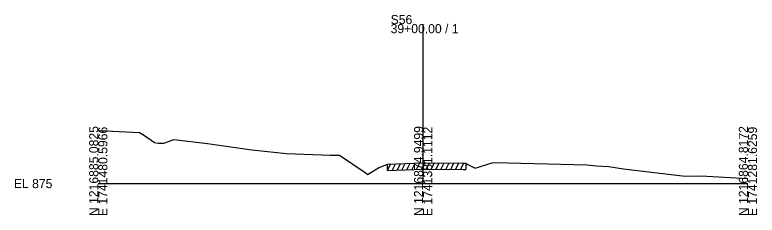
# Model space of a CAD drawing. Extents: x -26 to 1203, y -10 to 19541.
# Drawn here: x -25.7 to 202.8, y 13990.3 to 14051.9 of the extents above; entities that cross this region are included whole.
import ezdxf

# ---------------------------------------------------------------- set-up
doc = ezdxf.new("R2010")
doc.units = 0
for name, color, linetype in [('RD_GPK_XS_Cell', 7, 'Continuous'), ('RD_XS_ExGround', 7, 'Continuous'), ('RD_XS_ExPaveRet', 7, 'Continuous'), ('RD_XS_TX_Elev_EX', 7, 'Continuous')]:
    doc.layers.add(name, color=color, linetype=linetype)

msp = doc.modelspace()

# ---------------------------------------------------------------- linework, layer by layer
at = {"layer": 'RD_GPK_XS_Cell'}
for p, q in [((100, 14000), (100, 14049.04)), ((0, 14000), (100, 14000)), ((100, 14000), (200, 14000))]:
    msp.add_line(p, q, dxfattribs=at)
at = {"layer": 'RD_XS_ExGround'}
msp.add_lwpolyline([(0, 14016.35), (2.37, 14016.18), (12.64, 14015.72), (13.87, 14014.98), (17.32, 14012.67), (18.41, 14012.42), (20.14, 14012.39), (21.58, 14012.99), (23.3, 14013.59), (33.58, 14012.37), (47.28, 14010.35), (57.94, 14009.22), (71.37, 14008.75), (74.26, 14008.76), (82.17, 14003.37), (82.88, 14002.84), (86.24, 14004.86), (88.99, 14005.98), (100, 14006.39), (100.66, 14006.42), (112.33, 14006.32), (113.15, 14006.32), (113.73, 14005.88), (115.99, 14004.79), (121.23, 14006.4), (121.96, 14006.46), (150.5, 14005.77), (153.36, 14005.45), (157.22, 14005.25), (161.65, 14004.52), (180.7, 14002.31), (185.45, 14002.38), (200, 14001.53)], dxfattribs=at)
at = {"layer": 'RD_XS_ExPaveRet'}
for p, q in [((88.99, 14003.98), (90.01, 14006.02)), ((88.99, 14003.98), (88.99, 14005.98)), ((90.49, 14004.04), (91.51, 14006.07)), ((91.99, 14004.09), (93.01, 14006.13)), ((93.49, 14004.15), (94.51, 14006.19)), ((94.99, 14004.2), (96.01, 14006.24)), ((96.49, 14004.26), (97.51, 14006.3)), ((97.99, 14004.31), (99.01, 14006.35)), ((99.49, 14004.37), (100.52, 14006.41)), ((100.99, 14004.42), (101.99, 14006.41)), ((102.49, 14004.4), (103.49, 14006.39)), ((103.99, 14004.39), (104.99, 14006.38)), ((105.49, 14004.38), (106.49, 14006.37)), ((106.99, 14004.36), (107.99, 14006.35)), ((108.49, 14004.35), (109.49, 14006.34)), ((109.99, 14004.34), (110.99, 14006.33)), ((111.49, 14004.32), (112.49, 14006.32)), ((113.15, 14006.32), (113.15, 14004.32)), ((88.99, 14003.98), (100, 14004.39)), ((100, 14004.39), (100.66, 14004.42)), ((100.66, 14004.42), (112.33, 14004.32)), ((112.33, 14004.32), (113.15, 14004.32))]:
    msp.add_line(p, q, dxfattribs=at)

# ---------------------------------------------------------------- texts
at = {"layer": 'RD_GPK_XS_Cell'}
for s, p in [('S56', (90, 14049.04)), ('39+00.00 / 1', (90, 14046.24)), ('EL 875', (-26, 13998.6))]:
    msp.add_text(s, height=2.8, dxfattribs=at).set_placement(p)
for s, p in [('N 1216885.0825', (0, 13990)), ('E 1741480.5966', (2.8, 13990)), ('N 1216874.9499', (100, 13990)), ('E 1741381.1112', (102.8, 13990)), ('N 1216864.8172', (200, 13990)), ('E 1741281.6259', (202.8, 13990))]:
    msp.add_text(s, height=2.8, rotation=90, dxfattribs=at).set_placement(p)
at = {"layer": 'RD_XS_TX_Elev_EX'}
msp.add_text('878.19', height=0.1, rotation=90, dxfattribs=at).set_placement((100.1, 14006.39))

doc.saveas('drawing.dxf')
